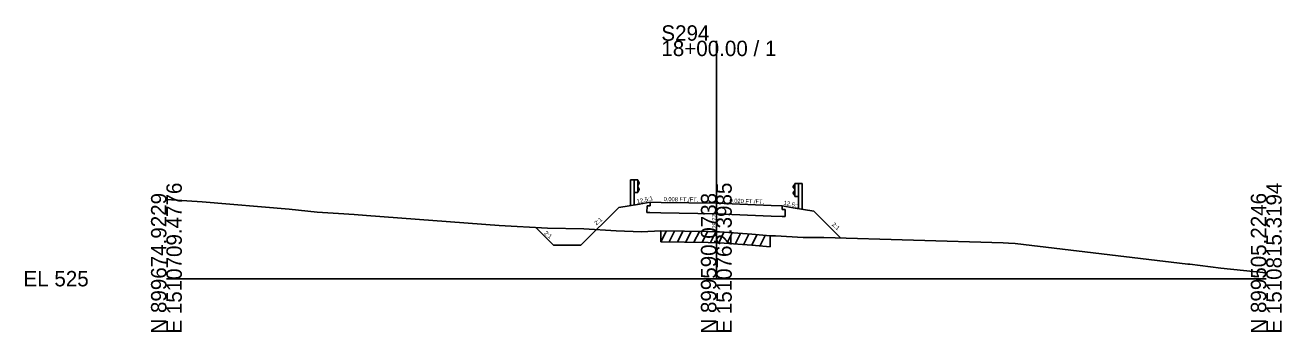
# Model space of a CAD drawing. Extents: x 974 to 2203, y -10 to 19041.
# Drawn here: x 974.3 to 1202.8, y 15990.3 to 16046.2 of the extents above; entities that cross this region are included whole.
import ezdxf

# ---------------------------------------------------------------- set-up
doc = ezdxf.new("R2010")
doc.units = 0
for name, color, linetype in [('RD_GPK_XS_Cell', 7, 'Continuous'), ('RD_XS_Base', 7, 'Continuous'), ('RD_XS_EarthShd', 7, 'Continuous'), ('RD_XS_ExGround', 7, 'Continuous'), ('RD_XS_ExPaveRet', 7, 'Continuous'), ('RD_XS_GR', 7, 'Continuous'), ('RD_XS_Pave', 7, 'Continuous'), ('RD_XS_TX_Elev_EX', 7, 'Continuous'), ('RD_XS_TX_Slope', 7, 'Continuous')]:
    doc.layers.add(name, color=color, linetype=linetype)

msp = doc.modelspace()

# ---------------------------------------------------------------- linework, layer by layer
at = {"layer": 'RD_GPK_XS_Cell'}
for p, q in [((1100, 16000), (1100, 16043.33)), ((1000, 16000), (1100, 16000)), ((1100, 16000), (1200, 16000))]:
    msp.add_line(p, q, dxfattribs=at)
at = {"layer": 'RD_XS_Base'}
for p, q in [((1087.38, 16012.02), (1087.45, 16013.29)), ((1087.96, 16013.28), (1087.45, 16013.29)), ((1087.96, 16013.28), (1087.99, 16013.92)), ((1087.88, 16012.02), (1087.38, 16012.02)), ((1087.88, 16012.02), (1089.88, 16011.98)), ((1089.88, 16011.98), (1099.95, 16011.82)), ((1110, 16011.41), (1099.95, 16011.82)), ((1112, 16011.33), (1110, 16011.41)), ((1112, 16012.6), (1112, 16013.24)), ((1112, 16012.6), (1112.5, 16012.58)), ((1112, 16011.33), (1112.5, 16011.31)), ((1112.5, 16011.31), (1112.5, 16012.58))]:
    msp.add_line(p, q, dxfattribs=at)
at = {"layer": 'RD_XS_EarthShd'}
for p, q in [((1086, 16013.59), (1082.25, 16012.96)), ((1087.99, 16013.92), (1085.99, 16013.58)), ((1075.38, 16006.1), (1082.24, 16012.96)), ((1112, 16013.24), (1114, 16012.91)), ((1114, 16012.91), (1117.75, 16012.28)), ((1122.64, 16007.39), (1117.75, 16012.28)), ((1070.38, 16006.1), (1067.19, 16009.29)), ((1075.38, 16006.1), (1070.38, 16006.1))]:
    msp.add_line(p, q, dxfattribs=at)
at = {"layer": 'RD_XS_ExGround'}
msp.add_lwpolyline([(1000, 16014.44), (1006.47, 16013.98), (1022.35, 16012.65), (1027.43, 16012.13), (1031.3, 16011.88), (1034.14, 16011.67), (1036.38, 16011.5), (1060.53, 16009.68), (1069.3, 16009.17), (1075.88, 16009.06), (1081.76, 16008.69), (1086.42, 16008.54), (1089.93, 16008.7), (1098.5, 16008.59), (1100, 16008.54), (1100.57, 16008.52), (1106.45, 16008.08), (1109.81, 16007.77), (1110.78, 16007.77), (1115.78, 16007.49), (1116.35, 16007.48), (1119.56, 16007.49), (1152.15, 16006.51), (1153.11, 16006.46), (1154.33, 16006.43), (1185.73, 16002.64), (1186.08, 16002.65), (1191.72, 16001.94), (1200, 16001.07)], dxfattribs=at)
at = {"layer": 'RD_XS_ExPaveRet'}
for p, q in [((1089.93, 16006.7), (1089.93, 16008.7)), ((1089.93, 16006.7), (1090.92, 16008.69)), ((1089.93, 16006.7), (1098.5, 16006.59)), ((1091.43, 16006.68), (1092.42, 16008.67)), ((1092.93, 16006.66), (1093.92, 16008.65)), ((1094.43, 16006.64), (1095.42, 16008.63)), ((1095.93, 16006.62), (1096.92, 16008.61)), ((1097.43, 16006.6), (1098.42, 16008.59)), ((1098.5, 16006.59), (1100, 16006.54)), ((1098.93, 16006.58), (1099.91, 16008.54)), ((1100, 16006.54), (1100.57, 16006.52)), ((1100.43, 16006.53), (1101.39, 16008.46)), ((1100.57, 16006.52), (1106.45, 16006.08)), ((1101.93, 16006.42), (1102.89, 16008.35)), ((1103.43, 16006.31), (1104.39, 16008.23)), ((1104.93, 16006.19), (1105.89, 16008.12)), ((1106.43, 16006.08), (1107.38, 16007.99)), ((1107.93, 16005.94), (1108.88, 16007.85)), ((1109.81, 16007.77), (1109.81, 16005.77)), ((1106.45, 16006.08), (1109.81, 16005.77))]:
    msp.add_line(p, q, dxfattribs=at)
at = {"layer": 'RD_XS_GR'}
for p, q in [((1084.39, 16018), (1084.39, 16013.23)), ((1085.06, 16018), (1084.39, 16018)), ((1085.06, 16018), (1085.06, 16013.35)), ((1085.72, 16018), (1085.06, 16018)), ((1085.72, 16015.67), (1085.72, 16018)), ((1085.72, 16017.86), (1085.99, 16017.46)), ((1085.72, 16015.67), (1085.05, 16015.67)), ((1085.99, 16017.36), (1085.72, 16016.96)), ((1085.99, 16016.31), (1085.72, 16016.71)), ((1085.72, 16015.81), (1085.99, 16016.21)), ((1085.99, 16017.46), (1085.99, 16017.36)), ((1085.99, 16016.21), (1085.99, 16016.31)), ((1114.27, 16017.18), (1114, 16016.78)), ((1114, 16016.78), (1114, 16016.68)), ((1114, 16016.68), (1114.27, 16016.28)), ((1114, 16015.64), (1114.27, 16016.04)), ((1114, 16015.54), (1114, 16015.64)), ((1114.27, 16017.32), (1114.94, 16017.32)), ((1114.27, 16014.99), (1114.27, 16017.32)), ((1114.94, 16017.32), (1114.94, 16012.67)), ((1114.94, 16017.32), (1115.6, 16017.32)), ((1115.6, 16017.32), (1115.6, 16012.56)), ((1114.27, 16015.14), (1114, 16015.54)), ((1114.27, 16014.99), (1114.94, 16014.99))]:
    msp.add_line(p, q, dxfattribs=at)
at = {"layer": 'RD_XS_Pave'}
for p, q in [((1087.99, 16013.92), (1089.99, 16013.88)), ((1089.99, 16013.88), (1100, 16013.72)), ((1110, 16013.32), (1100, 16013.72)), ((1112, 16013.24), (1110, 16013.32))]:
    msp.add_line(p, q, dxfattribs=at)

# ---------------------------------------------------------------- texts
at = {"layer": 'RD_GPK_XS_Cell'}
for s, p in [('S294', (1090, 16043.33)), ('18+00.00 / 1', (1090, 16040.53)), ('EL 525', (974, 15998.6))]:
    msp.add_text(s, height=2.8, dxfattribs=at).set_placement(p)
for s, p in [('E 1510709.4776', (1002.8, 15990)), ('E 1510762.3985', (1102.8, 15990)), ('E 1510815.3194', (1202.8, 15990)), ('N 899674.9229', (1000, 15990)), ('N 899590.0738', (1100, 15990)), ('N 899505.2246', (1200, 15990))]:
    msp.add_text(s, height=2.8, rotation=90, dxfattribs=at).set_placement(p)
at = {"layer": 'RD_XS_TX_Elev_EX'}
msp.add_text('529.27', height=0.75, rotation=90, dxfattribs=at).set_placement((1100, 16008.54))
at = {"layer": 'RD_XS_TX_Slope'}
for s, height, rotation, p in [('12.5:1', 0.778, 12.7511, (1085.61, 16013.66)), ('0.008 FT./FT.', 0.7518, 358.998, (1090.41, 16014.12)), ('0.020 FT./FT.', 0.7518, 357.7673, (1102.39, 16013.86)), ('12.5:1', 0.778, 347.2489, (1112.17, 16013.49)), ('2:1', 0.778, 40.6589, (1078.22, 16009.68)), ('2:1', 0.778, 319.3411, (1120.92, 16009.74)), ('2:1', 0.778, 319.3411, (1068.59, 16008.2))]:
    msp.add_text(s, height=height, rotation=rotation, dxfattribs=at).set_placement(p)

doc.saveas('drawing.dxf')
